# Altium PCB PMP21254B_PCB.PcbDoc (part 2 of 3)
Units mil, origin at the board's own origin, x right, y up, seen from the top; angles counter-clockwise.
Board outline 5000 x 7000 mil, 8 copper layers (Top Layer, Signal Layer 1, Signal Layer 2, Signal Layer 3, Signal Layer 4, Signal Layer 5, Signal Layer 6, Bottom Layer), stack 63 mil thick; 205 components, 78 nets, 623 pads, 1087 vias.
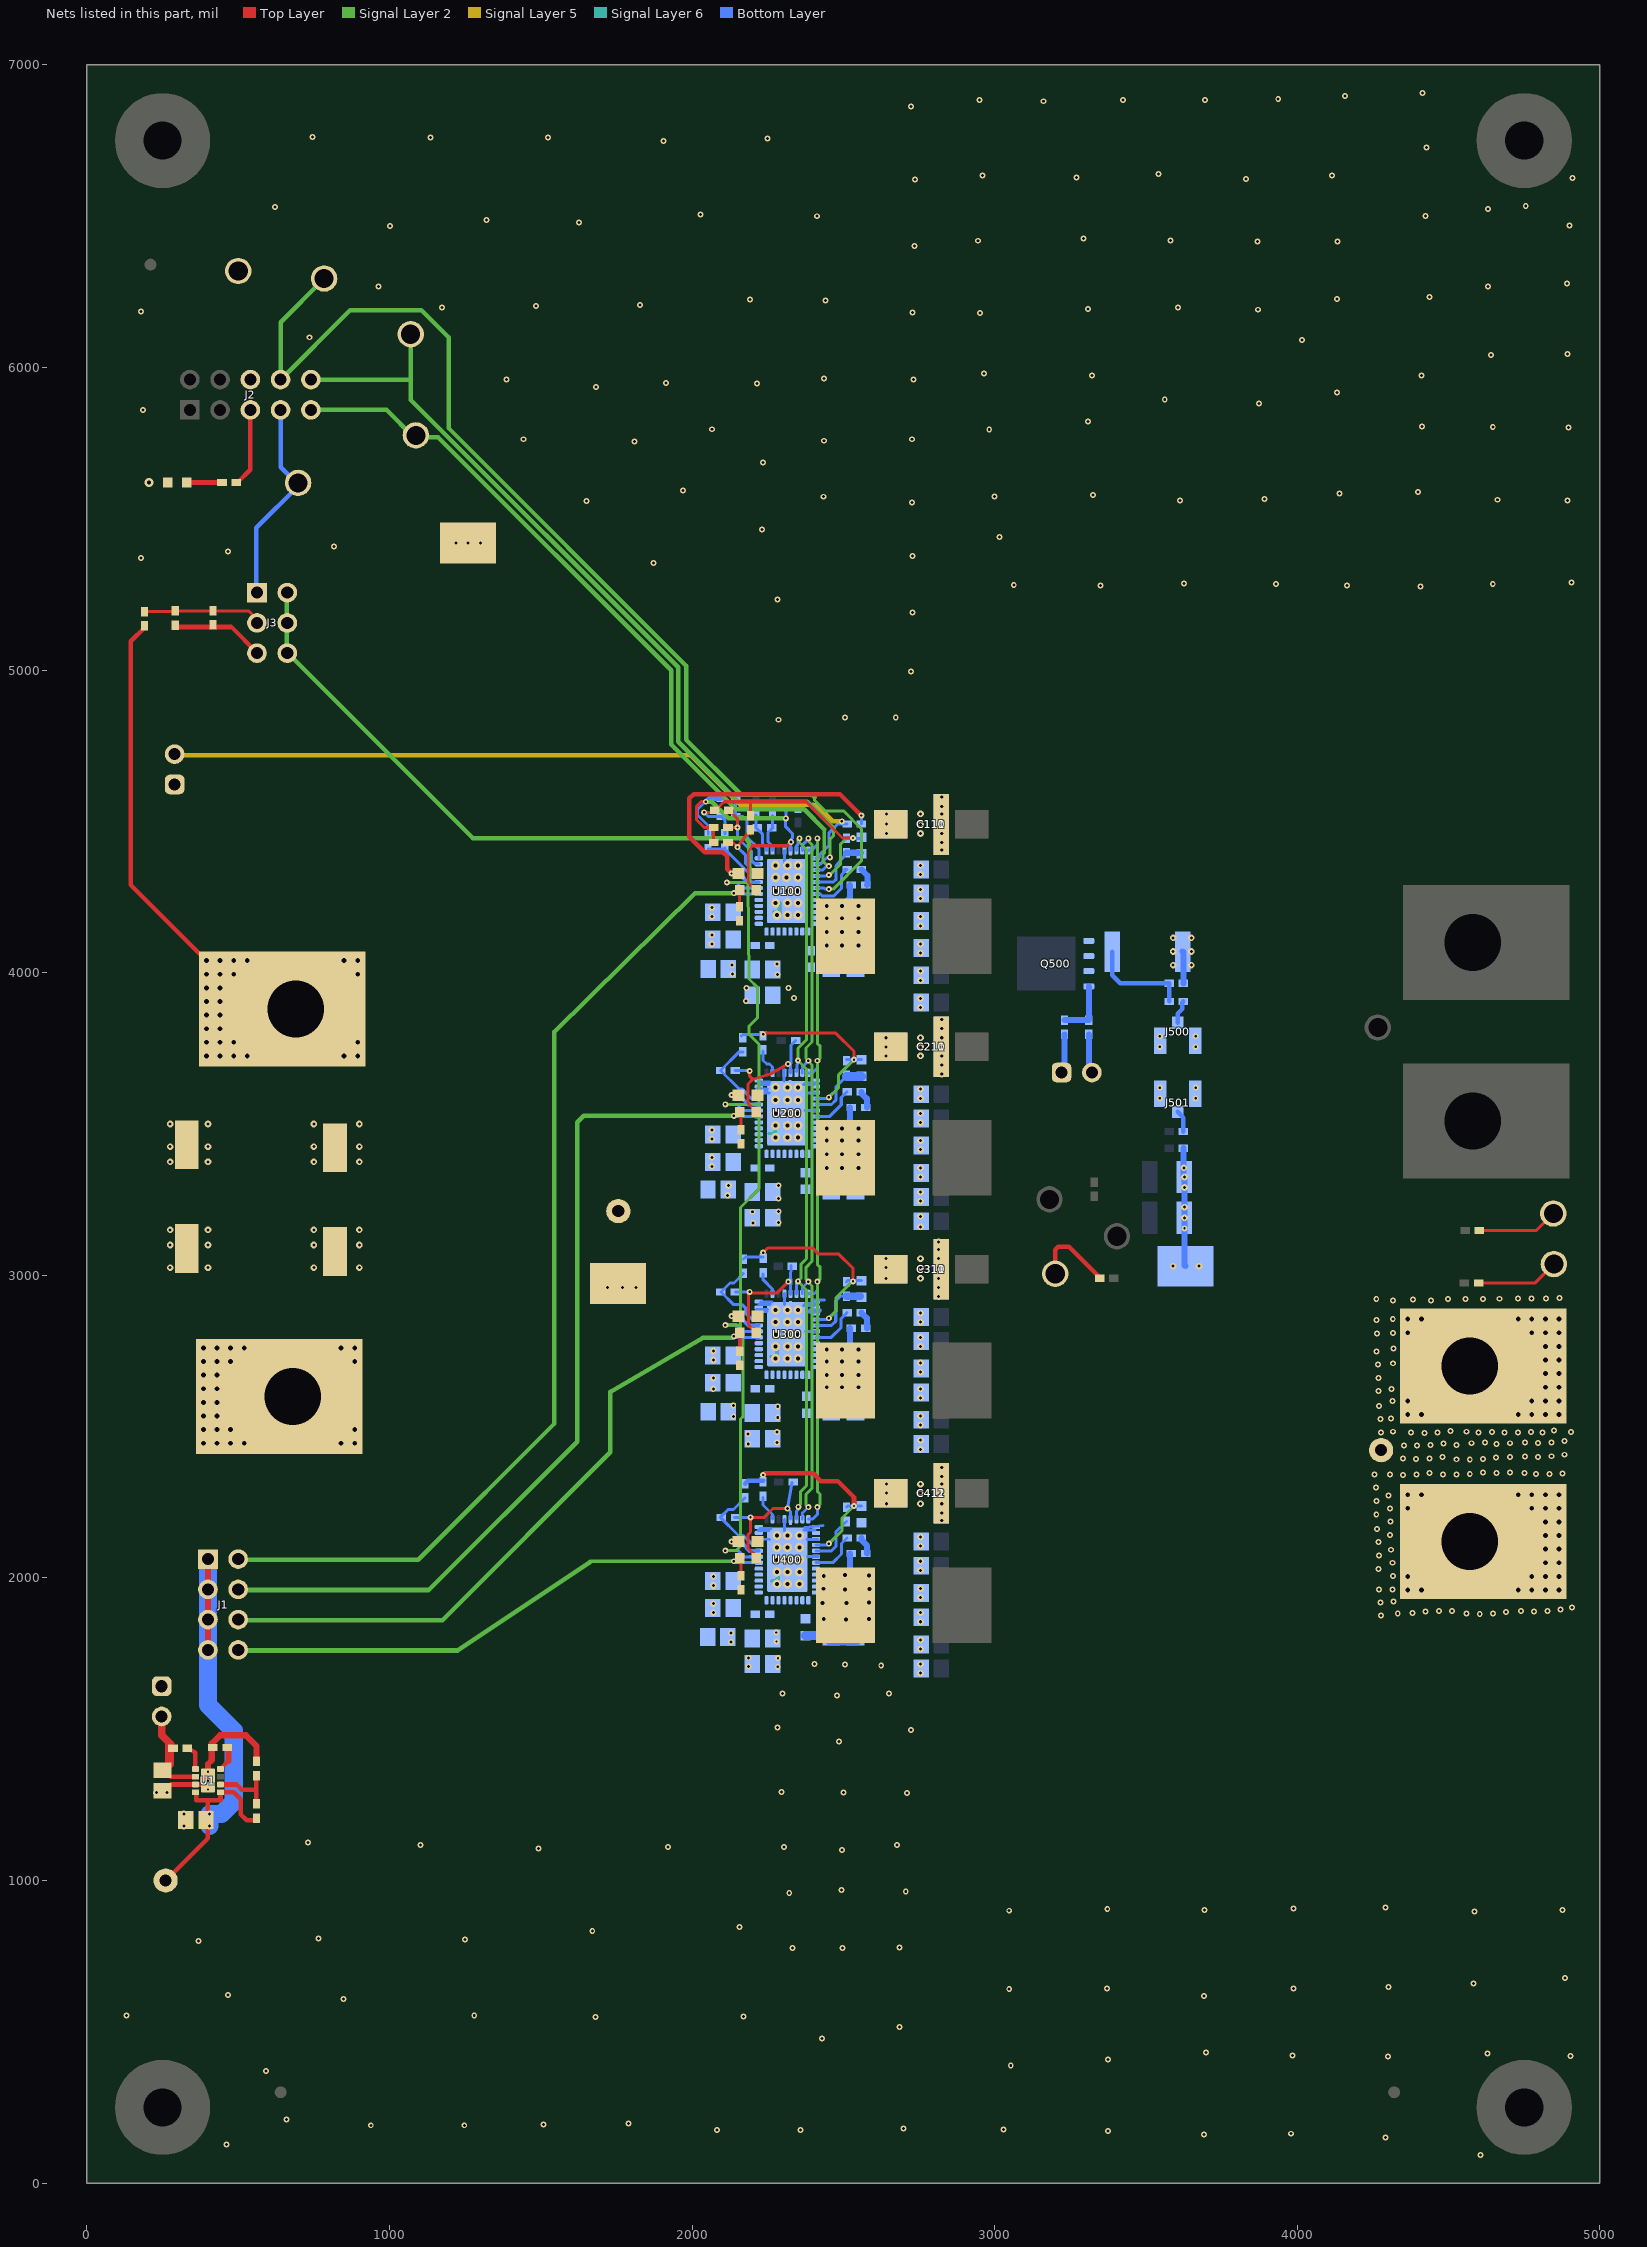
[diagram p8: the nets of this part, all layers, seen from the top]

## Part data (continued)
R105: library part CMP-0025958-3, "RES, 10.0 k, 1%, 0.063 W, AEC-Q200 Grade 0, 0402", Manufacturer=Vishay-Dale, PartNumber=CRCW040210K0FKED, Power_W=63mW, Supplier Part Number 1=541-10.0KLCT-ND, TempCo="100 ppm/C", Tolerance_%=1%, Value2=0.063W, Value_Code=10k0, ValueDisplayed=1.15k
R106: library part CMP-0025958-3, "RES, 10.0 k, 1%, 0.063 W, AEC-Q200 Grade 0, 0402", Manufacturer=Vishay-Dale, PartNumber=CRCW040210K0FKED, Power_W=63mW, Supplier Part Number 1=541-10.0KLCT-ND, TempCo="100 ppm/C", Tolerance_%=1%, Value2=0.063W, Value_Code=10k0, ValueDisplayed=5.62k
R108: library part CMP-0025958-3, "RES, 10.0 k, 1%, 0.063 W, AEC-Q200 Grade 0, 0402", Manufacturer=Vishay-Dale, PartNumber=CRCW040210K0FKED, Power_W=63mW, Supplier Part Number 1=541-10.0KLCT-ND, TempCo="100 ppm/C", Tolerance_%=1%, Value2=0.063W, Value_Code=10k0, ValueDisplayed=26.1k
R109 R503: library part CMP-0025958-3, "RES, 10.0 k, 1%, 0.063 W, AEC-Q200 Grade 0, 0402", Manufacturer=Vishay-Dale, PartNumber=CRCW040210K0FKED, Power_W=63mW, Supplier Part Number 1=541-10.0KLCT-ND, TempCo="100 ppm/C", Tolerance_%=1%, Value2=0.063W, Value_Code=10k0, ValueDisplayed=10.0k
R113 R213 R313 R413: library part CMP-0026822-3, "RES, 0, 5%, 0.063 W, AEC-Q200 Grade 0, 0402", Manufacturer=Vishay-Dale, PartNumber=CRCW04020000Z0ED, Power_W=63mW, Supplier Part Number 1=541-0.0JCT-ND, TempCo="200 ppm/C", Tolerance_%=5%, Value2=0.063W, Value_Code=0000, ValueDisplayed=0
R114 R115 R214 R215 R314 R315 R414 R415: library part CMP-0020547-3, "RES, 3.3, 5%, 0.125 W, AEC-Q200 Grade 0, 0805", Manufacturer=Vishay-Dale, PartNumber=CRCW08053R30JNEA, Power_W=125mW, Supplier Part Number 1=541-3.3ACT-ND, TempCo="200 ppm/C", Tolerance_%=5%, Value2=0.125W, Value_Code=3R30, ValueDisplayed=3.3
R202: library part CMP-0025958-3, "RES, 10.0 k, 1%, 0.063 W, AEC-Q200 Grade 0, 0402", Manufacturer=Vishay-Dale, PartNumber=CRCW040210K0FKED, Power_W=63mW, Supplier Part Number 1=541-10.0KLCT-ND, TempCo="100 ppm/C", Tolerance_%=1%, Value2=0.063W, Value_Code=10k0, ValueDisplayed=6.81k
R402: library part CMP-0025958-3, "RES, 10.0 k, 1%, 0.063 W, AEC-Q200 Grade 0, 0402", Manufacturer=Vishay-Dale, PartNumber=CRCW040210K0FKED, Power_W=63mW, Supplier Part Number 1=541-10.0KLCT-ND, TempCo="100 ppm/C", Tolerance_%=1%, Value2=0.063W, Value_Code=10k0, ValueDisplayed=31.6k
R500: library part CMP-0015807-2, "RES, 0.01, 1%, 1 W, 2512", Manufacturer=Panasonic, PartNumber=ERJ-M1WSF10MU, Power_W=1W, Supplier Part Number 1=P10MCT-ND, TempCo="100 ppm/C", Tolerance_%=1%, Value_Code=R010, ValueDisplayed=0.01
R502: library part CMP-0026866-3, "RES, 1.0, 5%, 0.063 W, AEC-Q200 Grade 0, 0402", Manufacturer=Vishay-Dale, PartNumber=CRCW04021R00JNED, Power_W=63mW, Supplier Part Number 1=541-1.0JCT-ND, TempCo="200 ppm/C", Tolerance_%=5%, Value2=0.063W, Value_Code=1R00, ValueDisplayed=1.0
T1 T2 T3 T4 T5 T6: library part CMP-0055442-1, "Terminal 50A Lug", Manufacturer=Panduit, Supplier Part Number 1=CB35-36-CY-ND, Voltage_V=600V
TP1 TP3: library part CMP-0055137-1, "Test Point, Miniature, Red, TH", Color=Red, Manufacturer=Keystone, Supplier Part Number 1=36-5000-ND
TP2 TP9 TP16: library part CMP-0055153-1, "Test Point, Compact, SMT", Manufacturer=Keystone, Supplier Part Number 1=36-5016TR-ND
TP4 TP11 TP15: library part CMP-0055148-1, "Test Point, Multipurpose, Black, TH", Color=Black, Manufacturer=Keystone, Supplier Part Number 1=36-5011-ND
TP5 TP6 TP7 TP8 TP12: library part CMP-0055149-1, "Test Point, Multipurpose, White, TH", Color=White, Manufacturer=Keystone, Supplier Part Number 1=36-5012-ND
TP10 TP13 TP14: library part CMP-0055147-1, "Test Point, Multipurpose, Red, TH", Color=Red, Manufacturer=Keystone, Supplier Part Number 1=36-5010-ND
TP17: library part CMP-0055138-1, "Test Point, Miniature, Black, TH", Color=Black, Manufacturer=Keystone, Supplier Part Number 1=36-5001-ND
U1: library part CMP-0074206-2, "3-A 17V Step-down Converter Module with Integrated Inductor, SIL0008D (uSIP-8)", Alternate Manufacturer="Texas Instruments", Alternate PartNumber=TPS82130SILT
U100 U200 U300 U400: library part CMP-0860534-2, "2.95-16V 40A PMBUS Stackable Synchronous Buck Converter, RVF0040A (LQFN-CLIP-40)", Alternate Manufacturer="Texas Instruments"

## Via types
v1: diameter 19.68, hole 9.84, Top Layer to Bottom Layer, 427 vias
v2: diameter 22, hole 10, Top Layer to Bottom Layer, tented both sides, 225 vias
v3: diameter 30, hole 13, Top Layer to Bottom Layer, tented both sides, 171 vias
v4: diameter 32, hole 16, Top Layer to Bottom Layer, 168 vias
v5: diameter 19.68, hole 7.87, Top Layer to Bottom Layer, tented bottom, 35 vias
v6: diameter 19.68, hole 7.87, Top Layer to Bottom Layer, tented both sides, 27 vias
v7: diameter 19.68, hole 7.87, Top Layer to Bottom Layer, 22 vias
v8: diameter 22, hole 10, Top Layer to Bottom Layer, tented bottom, 6 vias
v9: diameter 19.68, hole 7.87, Top Layer to Bottom Layer, tented top, 5 vias
v10: diameter 19.68/19.68/19.68/19.68/19.68/19.68/19.68/19.68 (per signal layer), hole 7.87, Top Layer to Bottom Layer, tented both sides, 1 vias

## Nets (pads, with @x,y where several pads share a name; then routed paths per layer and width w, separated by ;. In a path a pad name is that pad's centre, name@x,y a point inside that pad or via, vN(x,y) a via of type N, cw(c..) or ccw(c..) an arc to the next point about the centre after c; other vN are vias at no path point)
5.3V: C5.1 J1.1 J1.3 J1.5 J1.7 R2.2 TP3.1 U1.4 U1.5 | length 1915.9
  Top Layer w15: TP3.1@260,1000 400,1140 400,1200 400,1265 ; U1.4@358.66,1291.61 361,1289.27 361,1265 400,1265 ; R2.2@560,1198.5 527.56,1198.5 508,1218.06 508,1269 485.39,1291.61 U1.5@441.34,1291.61 441.34,1265.81 440.52,1265 400,1265
  Top Layer w20: J1.7@400,1760 400,1860 400,1960 J1.1@400,2060
  Bottom Layer w60: J1.1@400,2060 400,1960 400,1860 400,1760 400,1580 485,1495 485,1260 445,1220 v2(405,1220) v2(405,1180)
avin_f1: C220.1 J1.4 R200.2 U200.26 | length 3048.9
  Top Layer w10: C220.1@2157.44,3540 2161,3536.44 R200.2@2161,3481.62
  Signal Layer 2 w15: J1.4@500,1960 1130,1960 1620,2450 1620,3505.43 1641.57,3527 v10(2137.76,3527)
  Bottom Layer w10: v10@2137.76,3528 2140.6,3525.16 U200.26@2220.51,3525.16
avin_f2: C320.1 J1.6 R300.2 U300.26 | length 2261.3
  Top Layer w10: R300.2@2157.44,2749.62 C320.1@2157.44,2810
  Signal Layer 2 w15: J1.6@500,1860 1175,1860 1730,2415 1730,2615 2035,2793 2132.76,2793 v6(2137.76,2798)
  Bottom Layer w10: v6@2137.4,2795.16 U300.26@2220.51,2795.16
avin_f3: C420.1 J1.8 R400.2 U400.26 | length 1871.6
  Top Layer w10: C420.1@2157.44,2065 2162,2060.44 R400.2@2162,2007.62
  Signal Layer 2 w10: 1663,2053 1665,2055 v6(2137.76,2055)
  Signal Layer 2 w15: J1.8@500,1760 1225,1760 1663,2053
  Bottom Layer w10: v6(2137.76,2055) 2142.6,2050.16 U400.26@2220.51,2050.16
avin_l: C120.1 J1.2 R100.2 U100.26 | length 3442.7
  Top Layer w10: R100.2@2157,4218.2 2157,4272.56 C120.1@2157.44,4273
  Signal Layer 2 w15: J1.2@500,2060 1095,2060 1545,2510 1545,3805 2009.57,4263 v6@2134.57,4263
  Bottom Layer w10: v6(2137.76,4263) 2140.6,4260.16 U100.26@2220.51,4260.16
BC_CLK: U100.39 U200.39 U300.39 U400.39 | length 2451.1
  Signal Layer 2 w10: v5(2384,2234) 2376.28,2241.72 2376.28,2276.28 2396.13,2296.13 2396.13,2964.75 2384,2976.87 v5(2384,2979) 2377,2986 2377,3027 2396.13,3046.13 2396.13,3694.75 2384,3706.87 v7(2384,3709) 2376.28,3716.72 2376.28,3751.01 2396,3770.72 2396,4423 2384,4435 v7(2384,4444)
  Bottom Layer w9: U400.39@2364.21,2193.86 2364.21,2214.21 v5(2384,2234) ; U300.39@2364.21,2938.86 2364.21,2959.21 v5(2384,2979) ; U200.39@2364.21,3668.86 2364.21,3689.21 v7(2384,3709)
  Bottom Layer w10: U100.39@2364.21,4403.86 2364.21,4412.68 2367.24,4424.12 2384,4440.87 v7(2384,4444)
BC_DAT: U100.40 U200.40 U300.40 U400.40 | length 2476.9
  Signal Layer 2 w10: v5(2414,2234) 2422.72,2242.72 2422.72,2277.28 2414,2286 v5(2414,2979) 2423,2988 2423,3027 2414,3036 v7(2414,3709) 2423,3718 2423,3757 2414,3766 v7(2414,4444)
  Bottom Layer w10: U400.40@2383.9,2193.86 2398.19,2193.86 2414,2209.67 v5(2414,2234) ; U300.40@2383.9,2938.86 2385.04,2940 2404.25,2940 2414,2949.75 v5(2414,2979) ; U200.40@2383.9,3668.86 2398.11,3668.86 2414,3684.75 v7(2414,3709) ; U100.40@2383.9,4403.86 2386.04,4406 2397,4406 2414,4423 v7(2414,4444)
CNTL: J2.7 J3.1 TP7.1 | length 682.8
  Bottom Layer w15: J3.1@560,5260 560,5470 700,5610 640,5670 J2.7@640,5860
Enable: J3.2 J3.4 J3.6 U100.27 U200.27 U300.27 U400.27 | length 5147.2
  Signal Layer 2 w10: v6(2110,2090) 2145,2090 2160,2105 2160,2525 2168.87,2533.87 2168.87,2814.13 2160,2823 2160,2835 ; v6(2110,2835) 2160,2835 ; v6(2110,3565) 2220.51,3565 ; v6(2115,4298) 2184.81,4298 ; 2189.02,4297 2188.02,4298 2184.81,4298 ; 2160,2835 2160,3224.18 2220.51,3284.7 2220.51,3565 ; 2184.81,4298 2188.34,3979 2216.73,3950.6 2216.73,3851.84 2188.02,3823.12 2188.02,3796.62 2221,3763.64 2221,3755 2220.51,3565
  Signal Layer 2 w15: J3.2@660,5260 660,5060 1275,4445 2175,4445 2189.02,4430.98 2189.02,4297
  Bottom Layer w10: v6(2110,2090) 2152.02,2090 2172.37,2069.65 2188.83,2069.65 2189.02,2069.84 U400.27@2220.51,2069.84 ; v6(2110,2835) 2148,2835 2168.16,2814.84 U300.27@2220.51,2814.84 ; v6(2110,3565) 2148,3565 2168.16,3544.84 U200.27@2220.51,3544.84 ; v6(2115,4298) 2147,4298 2165.16,4279.84 U100.27@2220.51,4279.84
F1_AGND: C220.2 C224.2 NT200.1 R202.1 U200.37 | length 449.3
  Top Layer w10: v5(2190,3675) 2190,3658.26 2200.38,3647.87 ; C220.2@2212.56,3540 2185,3567.56 2185,3632.49 2200.38,3647.87 ; v1(2317,3699) 2259,3665.05 2200.38,3647.87
  Bottom Layer w10: R202.1@2141.24,3677 2188,3677 v5(2190,3675) ; U200.37@2324.84,3668.86 2324.84,3697.72 2326.72,3699.59 2326.72,3760.47 C224.2@2342.24,3776
F1_BP1V5: C222.1 C223.1 R201.1 R219.1 U200.4 | length 683.4
  Top Layer w10: v7(2234.45,3796.08) 2238.37,3800 2475,3800 2535,3740 v7(2535,3712.56)
  Signal Layer 2 w10: v6(2452,3588) 2483.33,3619.33 2483.33,3660.89 v7(2535,3712.56)
  Bottom Layer w10: R201.1@2162.52,3790.62 2167.98,3796.08 v7(2234.45,3796.08) ; U200.4@2409.49,3584.21 2448.21,3584.21 v6(2452,3588) v6@2450.79,3589.21 ; C222.1@2510,3712.56 v7(2535,3712.56) C223.1@2560,3712.56
F2_AGND: C320.2 C324.2 NT300.1 R302.1 U300.37 | length 434.6
  Top Layer w10: C320.2@2212.56,2810 2185.81,2836.75 2185.81,2940.81 2279.81,2940.81 v5(2318,2979)
  Bottom Layer w10: R302.1@2142.62,2945 v5(2190,2945) ; U300.37@2324.84,2936.26 U300.37@2324.84,2938.86 2324.84,2967.72 2326.72,2969.59 2326.72,2988.41 2324.84,2990.28 C324.2@2326.38,3032
F2_BP1V5: C322.1 C323.1 R301.1 R319.1 U300.4 | length 693.1
  Top Layer w10: v5(2235,3075) 2250,3090 2398.62,3090 2418.62,3070 2485,3070 2531.65,3023.35 v5(2531.65,2980)
  Signal Layer 2 w10: v6(2452,2858) 2475,2881 2475,2925 2530,2980 v5(2531.65,2980)
  Bottom Layer w10: R301.1@2170,3053.62 2176.34,3059.96 R319.1@2235,3059.96 ; U300.4@2409.49,2854.21 2448.21,2854.21 v6(2452,2858) ; C322.1@2510,2978.62 2513.94,2982.56 C323.1@2560,2982.56
F3_AGND: C420.2 C424.2 NT400.1 R402.1 U400.37 | length 463
  Top Layer w10: C420.2@2212.56,2065 2212.56,2069.49 2185.13,2096.92 2185.13,2143.18 2193,2151.06 v5(2193,2200) 2238.5,2200 2267.5,2229 v1(2315,2229)
  Bottom Layer w10: R402.1@2140.62,2200 v5(2193,2200) ; U400.37@2324.84,2193.86 2324.84,2219.16 v1(2315,2229) C424.2@2330,2315.43
F3_BP1V5: C422.1 C423.1 R401.1 R419.1 U400.4 | length 706.9
  Top Layer w15: v5(2235,2340) 2240.22,2345.22 2400.22,2345.22 2425.43,2320 2481.65,2320 2535,2266.65 v5(2535,2237.56)
  Signal Layer 2 w10: v9(2452,2113) 2495,2156 2495,2197.56 v5(2535,2237.56)
  Bottom Layer w10: U400.4@2409.49,2109.21 2448.21,2109.21 v9(2452,2113) ; C422.1@2510,2233.62 2513.94,2237.56 C423.1@2560,2237.56 v5(2535,2237.56)
  Bottom Layer w15: R401.1@2175,2311.62 2184.46,2321.08 R419.1@2234.49,2321.08
GND: C1.2 C2.2 C3.2 C4.2 C5.2 C7.1 C10.1 C11.1 C100.1 C101.1 C102.1 C103.1 C104.1 C105.2 C109.2 C110.2 C110.3 C111.2 C111.3 C112.2 C113.2 C114.2 C115.2 C116.2 C117.2 C121.1 C200.2 C201.1 C202.1 C203.1 C204.1 C205.2 C209.2 C210.2 C210.3 C211.2 C211.3 C212.2 C213.2 C214.2 C215.2 C216.2 C217.2 C221.1 C300.2 C301.1 C302.1 C303.1 C304.1 C305.2 C309.2 C310.2 C310.3 C311.2 C311.3 C312.2 C313.2 C314.2 C315.2 C316.2 C317.2 C321.1 C400.2 C401.1 C402.1 C403.1 C404.1 C405.2 C409.2 C411.2 C411.3 C412.2 C412.3 C413.2 C414.2 C415.2 C416.2 C417.2 C418.2 C421.1 C500.2 C505.2 J2.6 J3.5 J500.2@3546.93,3775 J500.3@3663.07,3775 J501.2@3663.07,3600 J501.3@3546.93,3600 J502.2 JP1.1 LED1.1 NT100.2 NT200.2 NT300.2 NT400.2 R3.1 R7.1 R13.1 R500.1 R503.1 T2.1 T5.1 T6.1 TP2.1 TP4.1 TP9.1 TP15.1 TP16.1 TP17.1 U1.3 U1.9 U100.13 U100.14 U100.15 U100.16 U100.17 U100.18 U100.19 U100.20 U100.36 U100.41@2315,4270 U200.1 U200.2 U200.3 U200.6 U200.13 U200.14 U200.15 U200.16 U200.17 U200.18 U200.19 U200.20 U200.30 U200.31 U200.32 U200.36 U200.41@2315,3535 U300.1 U300.2 U300.3 U300.6 U300.13 U300.14 U300.15 U300.16 U300.17 U300.18 U300.19 U300.20 U300.30 U300.31 U300.32 U300.36 U300.41@2315,2805 U400.1 U400.2 U400.3 U400.6 U400.13 U400.14 U400.15 U400.16 U400.17 U400.18 U400.19 U400.20 U400.30 U400.31 U400.32 U400.36 U400.41@2315,2060 | length 3229.5
  Top Layer w15: C3.2@250,1290 277.2,1317.2 U1.3@358.66,1317.2 387.2,1317.2 v7(400,1330) ; R7.1@290,5142.44 477.56,5142.44 J3.5@560,5060 ; TP15.1@3200,3000 3200,3085 3210,3095 3245,3095 3342.44,2997.56 R13.1@3342.44,2995
  Top Layer w20: v7(400,1330) v7(400,1359.52) 400,1385 412.44,1397.44 412.44,1452.44 440,1480 525,1480 560,1445 R3.1@560,1401.49
  Signal Layer 6 w10: v2(2070,2720) v2@2075,2720 ; 2254.45,3468.52 2264.94,3468.52 ; 2260,2732.4 v3@2270.5,2732.4 ; 2264.39,1990 v3@2274.88,1990 ; v3@2270,4200 v3@2278.87,4200 ; v3@2274.45,3498.52 2274.94,3498.03 2274.94,3475 ; v3@2280,2762.4 2280.5,2761.9 2280.5,2740 ; v3@2284.39,2020 2284.88,2019.5 2284.88,1999.75 ; 2264.94,3468.52 2274.94,3458.52 2274.94,3475 ; 2264.94,3468.52 2268.47,3468.52 2274.94,3475 ; v3@2270.5,2732.4 2280.5,2722.4 2280.5,2740 ; v3@2270.5,2732.4 2272.9,2732.4 2280.5,2740 ; v3@2274.88,1990 2284.88,1980 2284.88,1999.75 ; v3@2274.88,1990 2275.13,1990 2284.88,1999.75 ; v3@2278.87,4200 2280.5,4200 2290.5,4190 2290.5,4229.5 2290,4230 2290,4211.13 v3@2278.87,4200
  Bottom Layer w10: U300.30@2210.3,2880 2246.8,2880 ; U200.30@2211.01,3608 2247.51,3608 ; 2212.11,2886.35 U300.41@2248.62,2886.35 ; 2212.11,3616.35 U200.41@2248.62,3616.35 ; 2217.34,2155.82 U400.41@2253.84,2155.82 ; 2217.34,3630.82 U200.41@2253.84,3630.82 ; U200.30@2219.66,3602 U200.41@2256.17,3602 ; 2220.77,2903 U300.41@2257.28,2903 ; U200.32@2220.77,3639 U200.41@2257.28,3639 ; U400.30@2222.5,2129.1 U400.41@2255.63,2126.76 ; U400.32@2223.75,2163.37 U400.41@2260.25,2163.37 ; U300.32@2226.75,2911 U300.41@2263.25,2911 ; 2304,3641.75 U200.36@2304,3678.25 ; U400.41@2305,2155.75 U400.36@2305,2192.25 ; U300.41@2305,2902.75 U300.36@2305,2939.25 ; U100.41@2305.16,4279.84 v3(2315,4270) ; U100.41@2305.16,4363.11 U100.36@2305.16,4403.86 ; U300.41@2368.61,2899.83 U300.2@2405.11,2899.83 ; U200.41@2368.61,3629.83 U200.2@2405.11,3629.83 ; U400.41@2369.75,2159 2406.25,2159 ; 2371.55,2166.3 2433,2172.46 ; U300.41@2372.4,2907 U300.1@2408.91,2907 ; U200.41@2372.99,3544.84 U200.6@2409.49,3544.84 ; U300.41@2374.54,2814 U300.6@2411.05,2814 ; U200.41@2374.54,3635 2411.05,3635 ; U200.41@2379.75,3602 U200.3@2416.25,3602 ; U400.41@2379.94,2127 U400.3@2416.44,2127 ; U400.41@2380.75,2070 U400.6@2417.25,2070 ; 2382.75,2879 U300.3@2419.25,2879 ; 2385.75,2880.59 2422.25,2880.59 ; 2387.75,2885.36 2424.25,2885.36 ; U300.1@2401.33,2918 2437.84,2918
  Bottom Layer w20: R503.1@3311.02,3796.38 3311.02,3680 J502.2@3321.02,3670 ; R500.1@3621.14,4070 3623.62,4067.52 C500.2@3623.62,3965 ; C505.2@3623.62,3420 3623.62,3328.46 v2(3627.09,3325) v2(3627.09,3190) 3627.09,3032.91 TP16.1@3630,3030
  other v1: 4606,92 461,128 4292,150 3691,161 3979,163 3374,172 2082,175 2358,175 3029,177 2699,180 938,191 1247,191 1509,194 1790,197 660,210 592,371 3053,389 3375,408 4300,418 4903,420 3984,421 4628,428 3699,432 2429,477 2686,516 1681,549 2170,551 130,554 1280,554 848,609 3691,618 466,622 3048,642 3371,643 3988,643 4301,648 4582,659 4884,677 2331,777 2497,777 2686,778 368,800 1250,805 766,808 1670,833 2156,846 4585,897 3048,900 3693,902 4876,903 3372,906 3987,908 4292,910 2321,959 2706,963 2493,968 2495,1100 1493,1106 1921,1111 2303,1111 1102,1117 2677,1117 731,1125 2710,1289 2501,1291 2296,1292 2484.83,1460 2723,1498 2281.61,1505 2479,1612 2299,1618 2650,1618 2625,1710 2505,1714 2405.06,1715 4277,1875 4603,1881 4332,1882 4559,1882 4647,1883 4381,1884 4690,1888 4424,1889 4783,1889 4512,1890 4739,1890 4468,1891 4827,1891 4870,1896 4908,1902 4275,1919 4318.1,1922 4270,1962 4315,1962 4316,2006 4269,2030 4314,2050 4270,2074 4309,2093 4268,2118 4307,2142 4263,2161 4308,2186 4261,2210 4306,2230 4262,2254 4301,2273 4260,2298 4350,2340 4255,2341 4306,2341 4526,2341 4394,2342 4482,2342 4570,2343 4833,2343 4789,2344 4877,2345 4751,2346 4437,2347 4658.57,2347 4613,2348 4702.57,2349 4570,2391 4526,2392 4393,2393 4614,2393 4349,2394 4437,2395 4657,2398 4703,2399 4480,2400 4796,2400 4752,2401 4840,2402 4883,2407 4396.35,2437 4352.35,2438 4440.35,2439 4526,2439 4659,2442 4483.35,2444 4576.35,2445 4703,2445 4796,2446 2280.4,2447 4620.35,2447 4752,2447 4840,2448 4883,2453 4420,2479 4376,2480 4599,2480 4729,2480 4277,2481 4464,2481 4685,2481 4811,2481 2280,2482 4643,2482 4773,2482 4904,2482 4317,2483 4559,2483 4507,2486 4848,2487 4275,2525 4309,2527 2283,2530 2283,2567 4270,2568 4314,2585 4268,2617 4312,2624 4269,2661 4267,2705 4315.88,2709.27 4262,2748 4318,2758 4263,2807.43 4316.08,2809 4261.81,2852 4315.53,2856 4317,2917 4442,2917 4382,2920 4613,2921 4261,2921.9 4498,2922 4556,2922 4668,2922.52 4730,2923 4774,2923 4822,2924 4866,2925 2284.86,3174 2285.47,3211 2286.18,3254.4 2286.05,3296.62 2337.27,3916 2318.62,3949 2281.61,3994 2280.4,4028.86 2285,4836 2505.44,4843 2673,4843 2724,4996 2728,5191 2281.61,5233 4407,5276 3349,5279 4164,5280 3063,5282 3929,5285 4646,5285 3625,5287 4906,5290 1872,5354 179,5370 2728,5377 466,5392 816,5408 3016,5440 2231,5465 2727,5554 1651,5559 3612,5560 4893,5560 4662,5563 3891,5566 2434,5573 3000,5574 3325,5579 4140,5584 4399,5589 1970,5593 2234.45,5686 1810,5756 2436,5758 1443,5763 2727,5763 2982,5795 2065,5796 4896,5802 4646,5803 4412,5805 3308,5821 185,5859 3873,5881 3562,5894 4131,5917 1683,5936 2214,5947 1913,5949 1386,5960 2731,5960 2436,5964 3321.02,5974 4411,5974 2964,5980 4640,6042 4893,6045 4015,6091 735,6100 2951,6180 2729,6182 178,6185 3870,6191 3308,6194 1174,6198 3605,6198 1484,6203 1828,6207 2441,6222 2191,6225 4131,6227 4437,6233 963,6268 4630,6268 4891,6277 2735,6402 3868,6417 4133,6417 2945,6419 3581,6420 3294,6427 1001.17,6468 4899,6469 1626,6479 1321,6487 2413,6500 4424,6501 2028,6506 4631,6524 622,6530 4755,6534 2736,6622 3831,6623 4909,6626 3271,6628 2959,6634 4115,6634 3541,6639 4427,6727 1905,6749 2249,6757 1135,6760 1523,6760 745,6762 2724,6863 3161,6880 2950,6884 3424,6884 3695,6884 3937,6888 4157,6897 4414,6907
  other v2: 320,1180 320,1220 230,1290 265,1290 2755,1685 2755,1715 2755,1765 2755,1795 2755,1855 2070,1885 2755,1885 2070,1915 2755,1935 2755,1965 2070,1975 2070,2005 2755,2025 2755,2055 2755,2105 2755,2135 2825,2190 2825,2215 2642.36,2245 2755,2245 2825,2245 2642.36,2280 2755,2280 2825,2280 2642.36,2310 2755,2310 2825,2310 2825,2335 2825,2365 2755,2425 2755,2455 2755,2505 2755,2535 2755,2595 2070,2625 2755,2625 2070,2660 2755,2680 2755,2710 2070,2750 2755,2765 2755,2795 2755,2845 2755,2875 2815,2930 1720,2960 1770,2960 1815,2960 2815,2960 2640,2990 2755,2990 2815,2990 275,3025 400,3025 750,3025 900,3025 2640,3025 2755,3025 2815,3025 3590,3030 3675,3030 2640,3055 2755,3055 2815,3055 2815,3085 275,3100 400,3100 750,3100 900,3100 2815,3110 275,3150 400,3150 750,3150 900,3150 2755,3160 2755,3195 3627.09,3225 2755,3245 2755,3275 3627.09,3290 2755,3325 2755,3355 3625,3355 2065,3360 2065,3390 2755,3415 2755,3445 2065,3450 2065,3480 2755,3505 2755,3535 2755,3585 2755,3615 2825,3665 2825,3695 2640,3725 2755,3725 2825,3725 2640,3755 2755,3755 2825,3755 2640,3785 2755,3785 2825,3785 2825,3815 2825,3845 2755,3885 2755,3915 2755,3975 2755,4005 2755,4065 2065,4095 2755,4095 2065,4125 2755,4155 2065,4185 2755,4185 2065,4215 2755,4245 2755,4275 2755,4325 2755,4355 2825,4405 2825,4430 2642.36,4460 2755,4460 2825,4460 2755,4490 2825,4490 2642.36,4491.46 2642.36,4525 2755,4525 2825,4525 2825,4550 2825,4580 1220,5420 1260,5420 1300,5420
  other v3: 2280,1980 2315,1980 2355,1980 2280,2020 2315,2020 2355,2020 2280,2060 2315,2060 2355,2060 2280,2100 2315,2100 2355,2100 2280,2140 2315,2140 2355,2140 2275.5,2725 2315,2725 2350,2725 2275,2765 2315,2765 2350,2765 2275,2805 2315,2805 2350,2805 2275,2845 2315,2845 2350,2845 2275,2885 2315,2885 2350,2885 2275.5,3455 2315,3455 2350,3455 2275,3495 2315,3495 2350,3495 2275,3535 2315,3535 2350,3535 2275,3580 2315,3580 2350,3580 2275,3620 2315,3620 2350,3620 2280,4190 2315,4190 2350,4190 2275,4230 2315,4230 2350,4230 2275,4270 2350,4270 2275,4315 2312,4315 2350,4315 2275,4355 2315,4355 2350,4355 205,5620
  other v4: 4365,1960 4410,1960 4730,1960 4775,1960 4820,1960 4865,1960 4365,2005 4775,2005 4820,2005 4865,2005 4820,2050 4865,2050 4820,2095 4865,2095 4820,2140 4865,2140 4820,2185 4865,2185 4365,2230 4775,2230 4820,2230 4865,2230 4365,2275 4410,2275 4730,2275 4775,2275 4820,2275 4865,2275 385,2445 430,2445 475,2445 520,2445 840,2445 885,2445 385,2490 430,2490 475,2490 885,2490 385,2535 430,2535 4365,2540 4410,2540 4730,2540 4775,2540 4820,2540 4865,2540 385,2580 430,2580 4365,2585 4775,2585 4820,2585 4865,2585 385,2625 430,2625 4820,2630 4865,2630 385,2670 430,2670 4820,2675 4865,2675 385,2715 430,2715 475,2715 885,2715 4820,2720 4865,2720 385,2760 430,2760 475,2760 520,2760 840,2760 885,2760 4820,2765 4865,2765 4365,2810 4775,2810 4820,2810 4865,2810 4365,2855 4410,2855 4730,2855 4775,2855 4820,2855 4865,2855
  other v5: 2283,1706 3627.09,3155 3545.94,3585 3664.05,3585 3545.94,3620 3665,3620 3545.95,3755 3664.06,3755 3545.95,3790 3664.06,3790
  other v6: 2284,1735 2279,1789.59 2278,1819.37
  other v7: 400,1300.47
  other v8: 3590,4025 3650,4025 3590,4070 3650,4070 3590,4115 3650,4115
L_AGND: C120.2 C124.2 NT100.1 R102.2 R104.2 R106.2 R108.2 U100.37 | length 1153
  Top Layer w8: 2199,4420.15 2185.13,4398.8 2185.13,4299.08 2192.56,4291.64 C120.2@2206.65,4276
  Top Layer w10: v6(2045,4565) 2030,4565 2015,4550 2015,4505 2040,4480 R106.2@2071.38,4480 R104.2@2071.38,4430
  Top Layer w12: 2199,4420.15 2314.28,4420.15 v1(2326.65,4432.53)
  Signal Layer 2 w15: v6(2045,4565) 2065,4565 2120,4510 v5(2310,4510)
  Bottom Layer w8: v6(2045,4565) 2044.29,4565 2018.28,4539 2018.28,4521 2053,4486.29 R102.2@2053,4456.62
  Bottom Layer w10: U100.37@2324.84,4403.86 2324.84,4430.72 v1(2326.65,4432.53) 2326.65,4434.53 2326.72,4434.59 2326.72,4440.99 2331.72,4445.99 2331.72,4459.21 2309,4481.93 2309,4509 v5(2310,4510) 2310,4535 2318.62,4543.62 C124.2@2350,4543.62
  Bottom Layer w15: v6(2045,4565) 2055,4575 2094.92,4575 R108.2@2096.38,4576.46
L_BP1V5: C122.1 C123.1 R101.1 R103.1 R105.1 R107.1 U100.4 | length 990.9
  Top Layer w10: v9(2040,4530) 2069.42,4530 2071.38,4531.96 2072.15,4531.96 2105.2,4565 2193,4565 ; R103.1@2193,4519 2193,4565 ; v6(2531.65,4445) 2497.23,4445 2377.23,4565 2193,4565
  Signal Layer 2 w10: v6(2452,4323) 2455.13,4323 2490,4357.87 2490,4423.62 2511.38,4445 v6(2531.65,4445)
  Bottom Layer w10: v9(2040,4530) 2053.54,4516.46 R107.1@2096.38,4516.46 2108,4504.83 R101.1@2108,4458.62 ; U100.4@2409.49,4319.21 2443.21,4319.21 2447,4323 v6(2452,4323) ; C122.1@2510,4443.62 2556.06,4443.62 C123.1@2560,4447.56
NetC3_1: C3.1 J9.2 R1.2 U1.2 | length 247.1
  Top Layer w15: C3.1@277.2,1342.79 U1.2@358.66,1342.79
  Top Layer w25: J9.2@247,1542 247,1479.37 276.38,1450
  Top Layer w30: C3.1@273,1385.11 R1.2@273,1446.61
NetC4_1: C4.1 U1.8 | length 72.5
  Top Layer w15: U1.8@441.34,1368.38 467.56,1394.6
  Top Layer w20: 467.56,1394.6 C4.1@467.56,1430
NetC7_2: C7.2 J3.3 R6.1 R7.2 | length 398.2
  Top Layer w10: R6.1@190,5193.62 289.68,5193.62 R7.2@291.68,5195.62 535.01,5195.62 J3.3@572,5158.63
NetC108_1: C108.1 R113.1 | length 60.8
  Bottom Layer w20: R113.1@2559.19,4341.46 2579.69,4320.96 2579.69,4292.13 C108.1@2577.56,4290
NetC108_2: C108.2 L100.1 R114.1 R115.1 U100.8 U100.9 U100.10 U100.11 U100.12 | length 81.4
  Bottom Layer w20: v3(2495,4220) 2522.44,4247.44 C108.2@2522.44,4290
  other v3: 2445,4090 2495,4090 2550,4090 2445,4135 2495,4135 2550,4135 2445,4180 2495,4180 2550,4180 2445,4220 2550,4220
NetC109_1: C109.1 R114.2 R115.2
NetC122_2: C122.2 C123.2 U100.5 | length 219.9
  Bottom Layer w10: U100.5@2409.49,4299.53 2467.53,4299.53 2475,4307 2475,4351.75 C122.2@2510,4394 ; C123.2@2556.06,4396.38 C123.2@2560,4392.44
  Bottom Layer w23: C122.2@2510,4396.38 C123.2@2556.06,4396.38
NetC125_1: C125.1 R111.2 U100.33 | length 131.1
  Bottom Layer w10: R111.2@2211,4520.44 2211,4479.44 2211.44,4479 2233.13,4457.31 2233.13,4425.34 2246.1,4412.37 U100.33@2246.1,4403.86
NetC125_2: C125.2 R112.2 U100.34 | length 128.4
  Bottom Layer w10: U100.34@2265.79,4403.86 2265.79,4417.96 2263.98,4419.77 2251,4432.75 2251,4463.44 2266.56,4479 2266,4479.56 R112.2@2266,4519.44
NetC208_1: C208.1 R213.1 | length 59.1
  Bottom Layer w20: R213.1@2559.19,3606.46 2559.19,3601.76 2577.56,3583.4 C208.1@2577.56,3555
NetC208_2: C208.2 L200.1 R214.1 R215.1 U200.8 U200.9 U200.10 U200.11 U200.12 | length 81.4
  Bottom Layer w20: v3(2495,3485) 2522.44,3512.44 C208.2@2522.44,3555
  other v3: 2445,3355 2495,3355 2550,3355 2445,3400 2495,3400 2550,3400 2445,3445 2495,3445 2550,3445 2445,3485 2550,3485
NetC209_1: C209.1 R214.2 R215.2
NetC222_2: C222.2 C223.2 U200.5 | length 214.5
  Bottom Layer w10: U200.5@2409.49,3564.53 2460.65,3564.53 2475,3578.87 2475,3622.44 C222.2@2510,3657.44
  Bottom Layer w30: C222.2@2510,3657.44 C223.2@2560,3657.44
NetC308_1: C308.1 R313.1 | length 59.1
  Bottom Layer w20: R313.1@2559.19,2876.46 2577.56,2858.09 C308.1@2577.56,2825
NetC308_2: C308.2 L300.1 R314.1 R315.1 U300.8 U300.9 U300.10 U300.11 U300.12 | length 90.2
  Bottom Layer w20: v3(2495,2755) 2510,2755 2522.44,2767.44 C308.2@2522.44,2825
  other v3: 2445,2630 2495,2630 2550,2630 2445,2670 2495,2670 2550,2670 2445,2715 2495,2715 2550,2715 2445,2755 2550,2755
NetC309_1: C309.1 R314.2 R315.2
NetC322_2: C322.2 C323.2 U300.5 | length 231
  Bottom Layer w10: U300.5@2409.49,2834.53 2460.65,2834.53 2474.72,2848.59 2474.72,2914.72 2491.38,2931.38 C322.2@2510,2931.38 ; C323.2@2556.06,2931.38 C323.2@2560,2927.44
  Bottom Layer w25: C322.2@2510,2931.38 C323.2@2556.06,2931.38
NetC408_1: C408.1 R413.1 | length 59.1
  Bottom Layer w20: R413.1@2559.19,2131.46 2559.19,2125.61 2577.56,2107.24 C408.1@2577.56,2080
NetC408_2: C408.2 L400.1 R414.1 R415.1 U400.8 U400.9 U400.10 U400.11 U400.12 | length 93.1
  Bottom Layer w20: v3@2495,2010 2515,2010 2522.44,2017.44 C408.2@2522.44,2080
  other v3: 2508,1863 2435,1864 2584.75,1864 2431,1917 2510,1917 2584.75,1918.23 2505.15,1962 2586,1963 2434,1964 2435,2006.84 2585,2008.23 2505,2010
NetC409_1: C409.1 R414.2 R415.2 | length 168.8
  Bottom Layer w10: R414.2@2452.26,1809.27 R414.2@2460,1801.54
  Bottom Layer w30: C409.1@2374.45,1809.27 R414.2@2452.26,1809.27
  Bottom Layer w50: R414.2@2460,1801.54 R415.2@2540,1801.54
NetC422_2: C422.2 C423.2 U400.5 | length 168.5
  Bottom Layer w10: U400.5@2409.49,2089.53 2460.65,2089.53 2475,2103.87 2475,2151.38 C422.2@2510,2186.38
NetC500_1: C500.1 Q500.1 Q500.2 Q500.3 R500.2 R501.1 | length 337.2
  Bottom Layer w15: R500.2@3388.86,4070 3388.86,3991.14 3415,3965 C500.1@3576.38,3965 R501.1@3576.38,3905
NetJ2_5: J2.5 R5.1 | length 257.6
  Top Layer w15: R5.1@497.56,5620 540,5662.44 J2.5@540,5860
NetJ500_1: J500.1 R501.2 | length 77.7
  Bottom Layer w15: J500.1@3605,3835.04 3605,3865 3620,3880 3620,3901.38 R501.2@3623.62,3905
NetJ501_1: J501.1 R505.1 | length 72.7
  Bottom Layer w15: J501.1@3605,3539.96 3623.62,3521.34 R505.1@3623.62,3475
NetJ502_1: J502.1 R502.1 | length 130.5
  Bottom Layer w20: J502.1@3221.02,3670 3231.02,3680 R502.1@3231.02,3796.38
NetLED1_2: LED1.2 R5.2 | length 110.9
  Top Layer w15: LED1.2@331.5,5620 R5.2@442.44,5620
NetQ500_4: Q500.4 R502.2 R503.2 | length 191.4
  Bottom Layer w20: R502.2@3231.02,3843.62 R503.2@3311.02,3843.62 3311.02,3954.96 Q500.4@3311.06,3955
NetR1_1: R1.1 U1.1 | length 85
  Top Layer w15: R1.1@331.62,1437 358.66,1422.83 U1.1@358.66,1368.38
NetR2_1: R2.1 R3.2 U1.6 | length 202.8
  Top Layer w15: U1.6@441.34,1317.2 495,1317.2 512.2,1300 560,1300 ; R2.1@560,1261.49 560,1300 ; R3.2@560,1338.5 560,1300
NetR10_2: R10.2 TP10.1 | length 267.6
  Top Layer w10: R10.2@4601.62,3148 4790,3148 TP10.1@4846,3204
NetR11_1: R11.1 TP11.1 | length 274.1
  Top Layer w10: R11.1@4599.62,2975 4786,2975 TP11.1@4848,3037
NetR101_2: R101.2 R102.1 U100.29 | length 207.9
  Bottom Layer w10: R102.1@2053,4409.38 2106,4409.38 R101.2@2108,4411.38 2108,4409.06 2197.85,4319.21 U100.29@2220.51,4319.21
NetR103_2: R103.2 R104.1 U100.30 | length 228.6
  Top Layer w10: R104.1@2118.62,4430 2135,4430 v9(2150,4415) R103.2@2185.91,4462.57 ; R103.2@2193,4458 R103.2@2193,4471.76
  Bottom Layer w10: v9(2150,4415) 2177.13,4387.87 2177.13,4361.15 2199.38,4338.9 U100.30@2220.51,4338.9
NetR105_2: R105.2 R106.1 U100.31 | length 243.3
  Top Layer w10: R105.2@2121.62,4537 2150,4508.62 v6(2150,4480) R106.1@2133.62,4480
  Bottom Layer w10: v6(2150,4480) 2150,4447.13 2196.73,4400.39 2196.73,4369.54 2204.89,4361.38 2217.72,4361.38 U100.31@2220.51,4358.58
NetR107_2: R107.2 R108.1 U100.32 | length 244.2
  Bottom Layer w10: R108.1@2143.62,4576.46 R107.2@2143.62,4516.46 2167.76,4516.46 2181.39,4502.82 2181.39,4448.61 2220.51,4409.49 U100.32@2220.51,4378.27
NetR113_2: R113.2 U100.7 | length 176.2
  Bottom Layer w10: U100.7@2409.49,4260.16 2423.95,4260.16 2423.95,4259.79 2430.87,4252.87 2467.56,4252.87 2493.82,4279.13 2493.82,4323.33 R113.2@2511.95,4341.46 R113.2@2504.03,4341.46
NetR201_2: R201.2 R202.2 U200.29 | length 263.9
  Bottom Layer w10: R201.2@2167.5,3738.38 2155.38,3738.38 2094,3677 2154.63,3616.37 2163.63,3616.37 2195.79,3584.21 U200.29@2220.51,3584.21
NetR213_2: R213.2 U200.7 | length 150.3
  Bottom Layer w10: U200.7@2409.49,3525.16 2454.84,3525.16 2459.84,3530.16 2492.87,3563.19 2492.87,3587.38 R213.2@2511.95,3606.46
NetR219_2: R219.2 U200.34 | length 93.5
  Bottom Layer w9: R219.2@2234.45,3740.96 2234.45,3710.55 2246.96,3698.04 2255.54,3698.04 2265.79,3687.79 U200.34@2265.79,3673.86 ; U200.34@2263.4,3676.25 U200.34@2265.79,3673.86 ; U200.34@2265.79,3668.86 U200.34@2265.79,3673.86
NetR301_2: R301.2 R302.2 U300.29 | length 262.2
  Bottom Layer w10: R301.2@2170,3006.38 2138.21,2974.59 2124.97,2974.59 R302.2@2095.38,2945 2137.38,2903 2165.62,2903 2177.13,2891.5 2177.13,2874.95 2196.05,2856.02 U300.29@2211,2856.02
NetR313_2: R313.2 U300.7 | length 153.4
  Bottom Layer w10: U300.7@2409.49,2795.16 2460.16,2795.16 2492.59,2827.59 2492.59,2857.1 R313.2@2511.95,2876.46
NetR319_2: R319.2 U300.34 | length 78.7
  Bottom Layer w10: R319.2@2235,3004.84 2235,2985 2265.79,2954.21 U300.34@2265.79,2938.86
NetR401_2: R401.2 R402.2 U400.29 | length 273
  Bottom Layer w10: R401.2@2175,2264.38 2136.62,2226 2119.38,2226 2093.38,2200 2153,2140.37 2168.84,2140.37 2200,2109.21 U400.29@2220.51,2109.21
NetR413_2: R413.2 U400.7 | length 156.4
  Bottom Layer w10: U400.7@2409.49,2050.16 2465.16,2050.16 2493.82,2078.82 2493.82,2113.33 R413.2@2511.95,2131.46
NetR419_2: R419.2 U400.34 | length 85.1
  Bottom Layer w10: R419.2@2234.49,2265.96 2234.49,2240.51 2265.79,2209.21 U400.34@2265.79,2193.86
PG_L: JP1.2 R109.2 U100.1 | length 2475.2
  Signal Layer 5 w15: JP1.2@290,4722.14 293.14,4719 1995,4719 2158.11,4555 2314.34,4555 2314.55,4555.22 2335.45,4555.22 2335.66,4555 2410,4555 2465,4500 v5(2495,4500)
  Bottom Layer w10: U100.1@2409.49,4378.27 U100.1@2409.49,4378.27 2416.71,4378.35 2421.36,4383 2421.36,4390.14 2453,4421.78 2453,4463 2481.46,4491.46 R109.2@2511.95,4491.46
PM_CLK: J2.9 TP6.1 U100.3 | length 2612.4
  Signal Layer 2 w10: 2436.72,4473.28 2436.72,4394.84 2432.28,4390.41 2432.28,4368.59 2448.87,4352 v6(2452,4352)
  Signal Layer 2 w15: J2.9@740,5860 990,5860 1080,5770 1160.3,5770 1930.8,4999.5 1930.8,4754.2 ; 1942.5,4742.5 1930.8,4754.2 ; 2436.72,4473.28 2370,4540 2145,4540 1930.8,4754.2
  Bottom Layer w10: U100.3@2409.49,4338.9 2430.77,4338.9 2443.87,4352 v6(2452,4352)
PM_DAT: J2.10 TP5.1 U100.2 | length 2882.1
  Signal Layer 2 w10: v6(2455,4381) 2455,4440 2467.23,4452.23 2467.23,4477.77
  Signal Layer 2 w15: J2.10@740,5960 1070,5960 ; 1070,5940 1070,5892.65 ; TP5.1@1070,6110 1070,5960 ; 2467.23,4477.77 2380,4565 2152.35,4565 1953.67,4763.67 1953.67,5008.98 1070,5892.65 ; 1070,5892.65 1070,5960
  Bottom Layer w10: U100.2@2409.49,4358.58 2423.59,4358.58 ; v6(2455,4381) 2446.01,4381 2425.48,4360.47 ; 2423.59,4358.58 2423.59,4360.47 2425.48,4360.47 ; 2423.59,4358.58 2425.48,4360.47
SMB_ALRT: J2.8 TP8.1 U100.6 | length 3735.7
  Signal Layer 2 w10: 2405,4580 2405,4568.81 2438.81,4535 2500,4535 2560,4475 2560,4370 2466,4276 v6(2452,4276)
  Signal Layer 2 w15: TP8.1@780,6290 640,6150 J2.8@640,5960 870,6190 1105,6190 1195,6100 1195,5800 1980,5015 1980,4769.7 2161.82,4587.87 2397.13,4587.87 2405,4580
  Bottom Layer w10: U100.6@2409.49,4279.84 2436.39,4279.84 2440.24,4276 v6(2452,4276)
Sync: U100.38 U200.38 U300.38 U400.38 | length 2446.7
  Signal Layer 2 w10: v5(2351,2235) 2358.41,2242.41 2358.41,2285.06 2378.25,2304.91 2378.25,2951.75 v5(2350,2980) 2359.13,2989.13 2359.13,3035.78 2378.25,3054.91 2378.25,3681.75 v7(2350,3710) 2350,3749.87 2352.72,3752.59 2352.72,3752.72 2378.13,3778.13 2378.13,4406.87 2355,4430 v6(2355,4444)
  Bottom Layer w10: U400.38@2344.53,2193.86 2344.53,2219.53 2351,2226 v5(2351,2235) ; U300.38@2344.53,2938.86 2344.53,2962.12 2344.59,2962.19 2344.59,2974.59 v5(2350,2980) ; U200.38@2344.53,3673.86 2346.42,3675.75 2346.42,3684.85 2346.84,3685.27 2346.84,3696.41 2350,3699.57 v7(2350,3710) ; U100.38@2344.53,4403.86 2344.53,4418.28 2349.37,4423.12 2349.37,4438.37 v6(2355,4444)
VDD5_1: C121.2 R109.1 U100.28 | length 1075.9
  Top Layer w15: v6(2130,4327.97) 2116,4341.97 2116,4384 2101.46,4398.54 2041.46,4398.54 1991.06,4448.94 1991.06,4576.06 2005.22,4590.22 2209.12,4590.22 2209.55,4589.78 2230.45,4589.78 2230.88,4590.22 2239.12,4590.22 2239.55,4589.78 2260.45,4589.78 2260.88,4590.22 2460.45,4590.22 2460.66,4590 2488.66,4590 v6(2559.19,4519.47)
  Bottom Layer w10: R109.1@2559.19,4491.46 v6(2559.19,4519.47)
  Bottom Layer w12: 2172.24,4310.72 2183.43,4299.53 U100.28@2220.51,4299.53
  Bottom Layer w15: v6(2130,4327.97) 2152.97,4327.97 2153.98,4328.98 2172.24,4310.72
VDD5_2: C221.2 U200.28 | length 103.5
  Bottom Layer w12: 2185.47,3564.53 U200.28@2220.51,3564.53
  Bottom Layer w13: 2154,3596 2185.47,3564.53
  Bottom Layer w15: v6(2130,3596) 2154,3596
VDD5_3: C321.2 U300.28 | length 103.1
  Bottom Layer w12: 2195,2834.53 U300.28@2220.51,2834.53
  Bottom Layer w13: 2155,2865 2185.47,2834.53 2195,2834.53
  Bottom Layer w15: v6(2130,2865) 2155,2865
VDD5_4: C421.2 U400.28 | length 103.1
  Bottom Layer w12: 2190,2089.53 U400.28@2220.51,2089.53
  Bottom Layer w13: 2169.53,2110 2190,2089.53
  Bottom Layer w15: v6(2130,2120) 2159.53,2120 2169.53,2110
Vin: C1.1 C2.1 C100.2 C101.2 C102.2 C103.2 C104.2 C105.1 C200.1 C201.2 C202.2 C203.2 C204.2 C205.1 C300.1 C301.2 C302.2 C303.2 C304.2 C305.1 C400.1 C401.2 C402.2 C403.2 C404.2 C405.1 J9.1 R6.2 R100.1 R200.1 R300.1 R400.1 T1.1 TP1.1 U100.21 U100.22 U100.23 U100.24 U100.25 U200.21 U200.22 U200.23 U200.24 U200.25 U300.21 U300.22 U300.23 U300.24 U300.25 U400.21 U400.22 U400.23 U400.24 U400.25 | length 1224.6
  Top Layer w15: R6.2@190,5142.44 190,5140 145,5095 145,4290 v4(395,4040)
  other v1: 2187,1707 2186,1736 2128,1788 2129,1818 2185.47,2443 2185,2475 2136,2534 2136,2569.14 2201,3173 2200,3210 2178.15,3907 2179,3949.4 2134,3996 2132.57,4026
  other v2: 2117.54,3264 2120,3297 275,3375 400,3375 750,3375 900,3375 275,3425 400,3425 750,3425 900,3425 275,3500 400,3500 750,3500 900,3500
  other v4: 395,3725 440,3725 485,3725 530,3725 850,3725 895,3725 395,3770 440,3770 485,3770 895,3770 395,3815 440,3815 395,3860 440,3860 395,3905 440,3905 395,3950 440,3950 395,3995 440,3995 485,3995 895,3995 440,4040 485,4040 530,4040 850,4040 895,4040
